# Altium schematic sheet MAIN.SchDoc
size A1; SheetNumber: 2; SheetTotal: 3
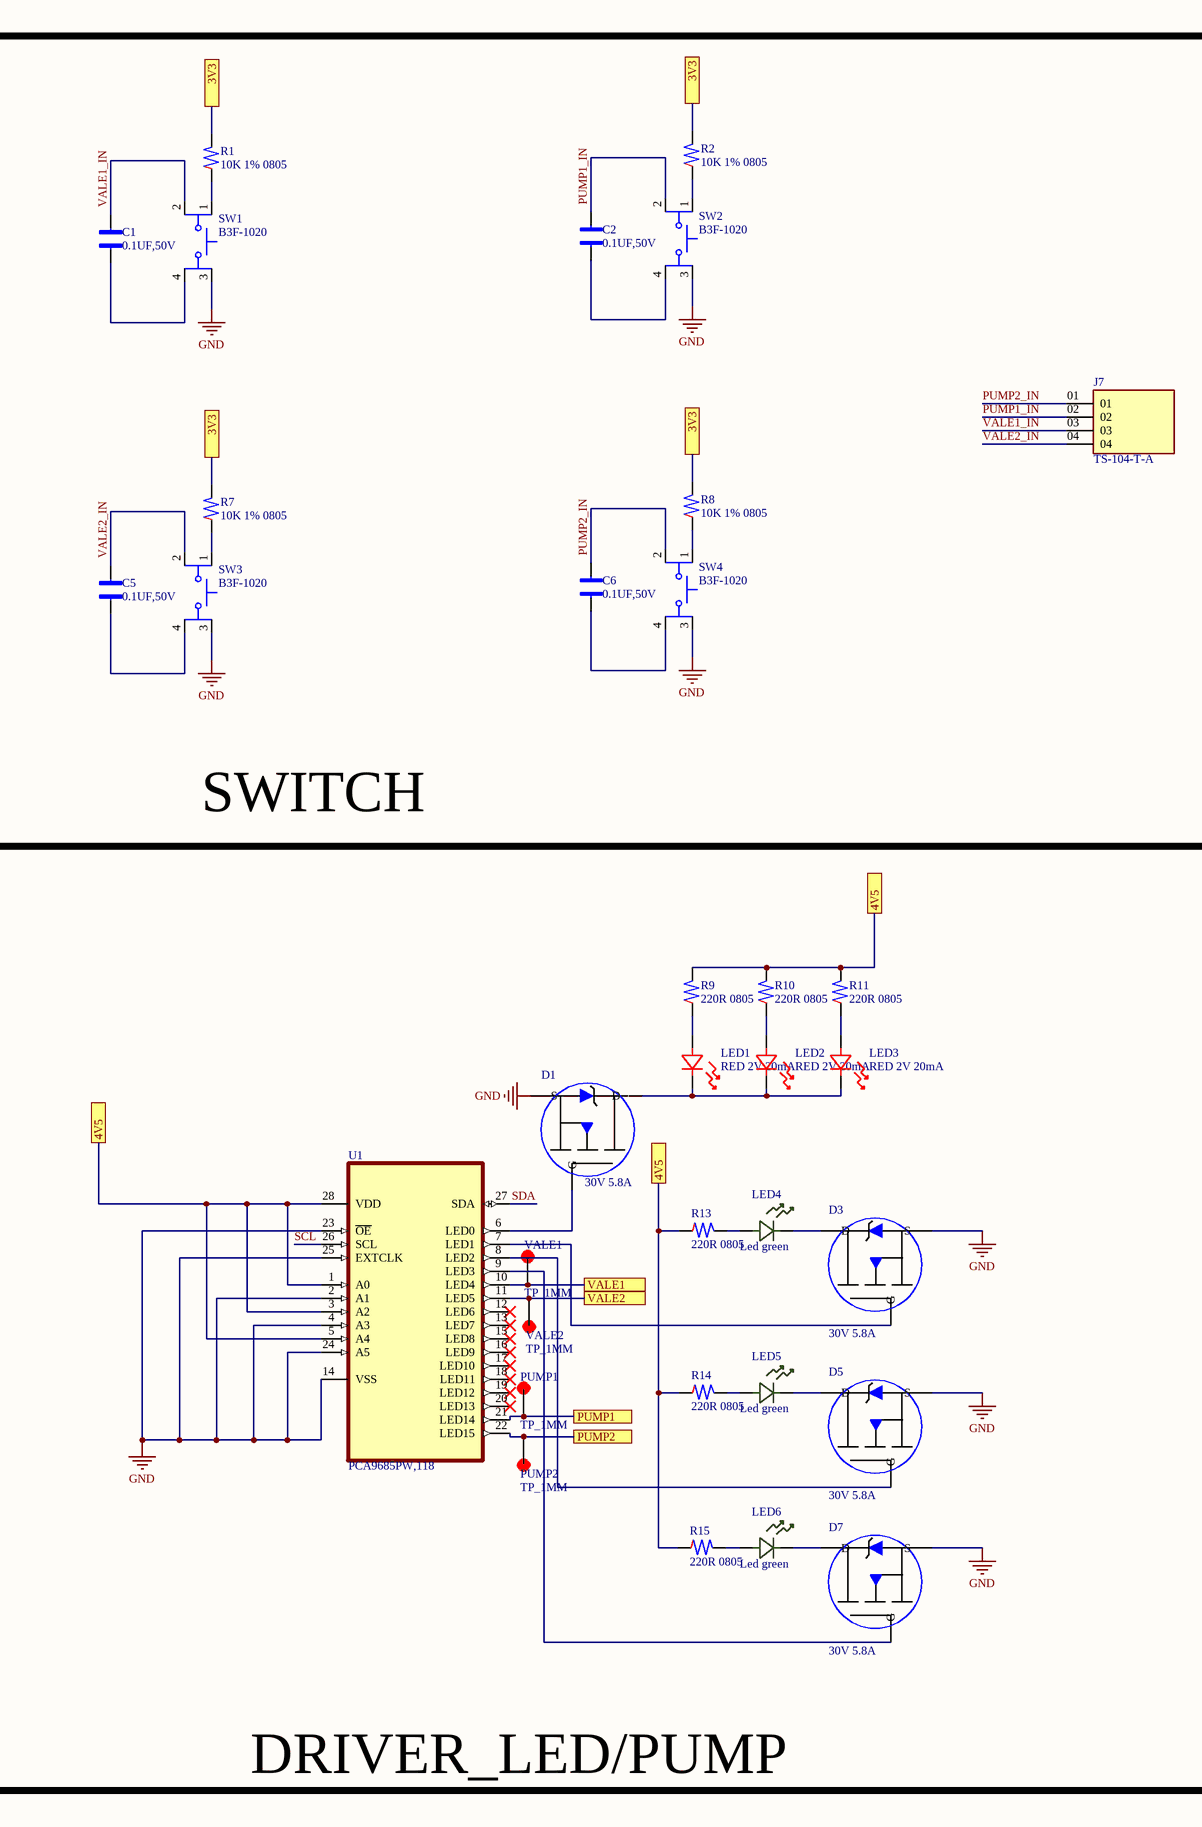
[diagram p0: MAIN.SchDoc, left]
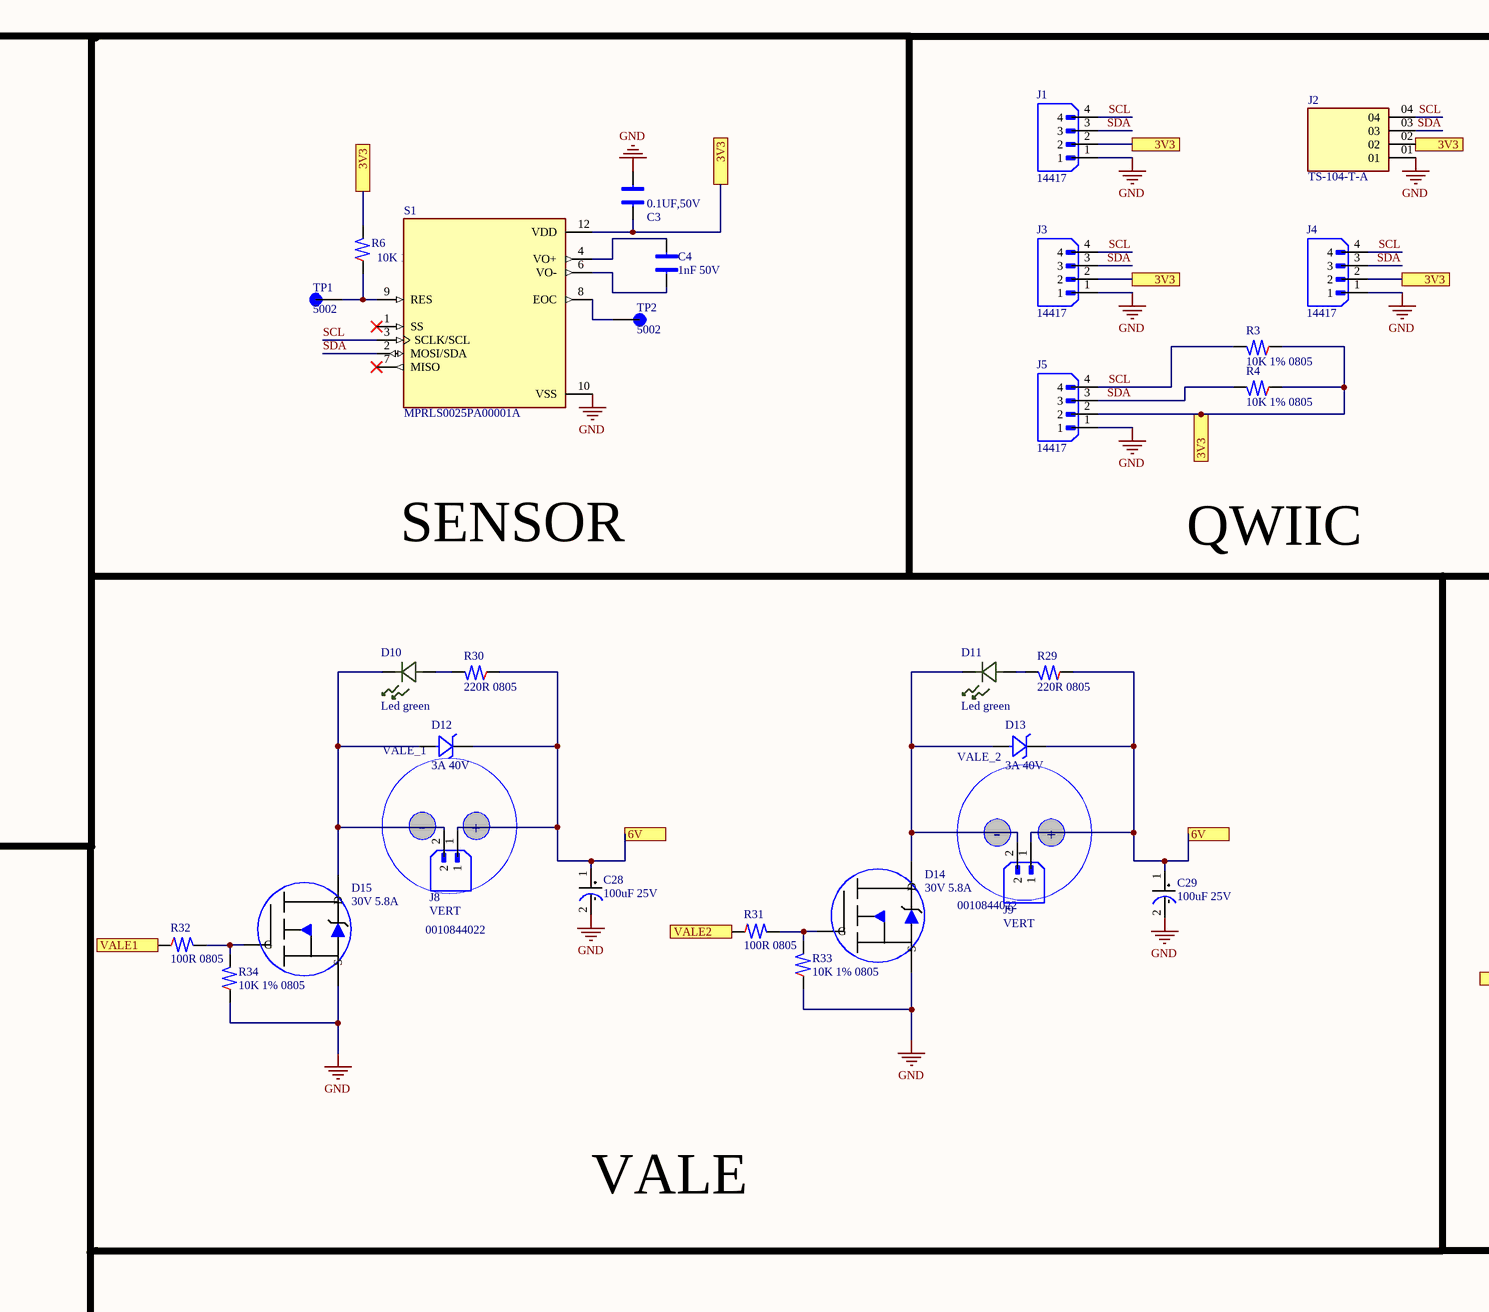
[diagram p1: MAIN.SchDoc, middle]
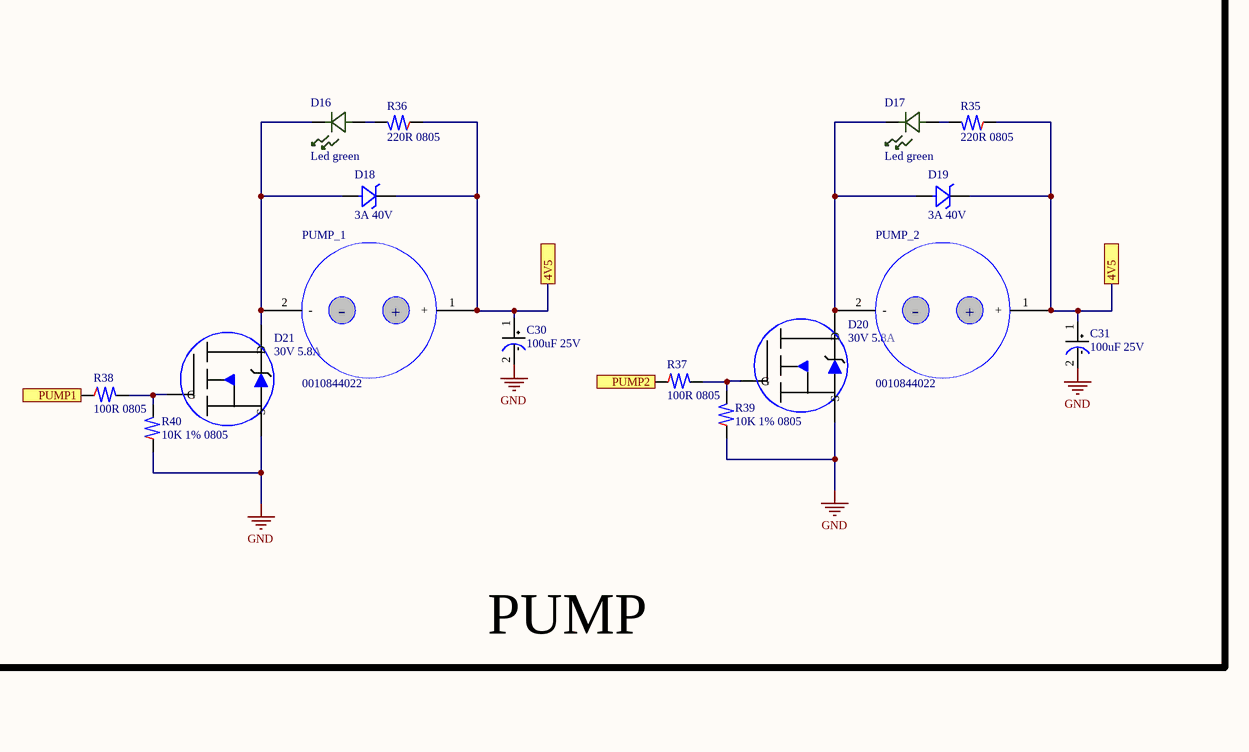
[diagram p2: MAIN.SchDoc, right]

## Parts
C1  0.1UF,50V  [CAP_CER_0805]
C2  0.1UF,50V  [CAP_CER_0805]
C3  0.1UF,50V  [CAP_CER_0805]
C4  1nF 50V  [CAP_CER_0805]
C5  0.1UF,50V  [CAP_CER_0805]
C6  0.1UF,50V  [CAP_CER_0805]
C28  100uF 25V  [CAP_ALUM_SMD_D10_H12.4]
C29  100uF 25V  [CAP_ALUM_SMD_D10_H12.4]
C30  100uF 25V  [CAP_ALUM_SMD_D10_H12.4]
C31  100uF 25V  [CAP_ALUM_SMD_D10_H12.4]
D1  30V 5.8A  [SOT-23-3]
D3  30V 5.8A  [SOT-23-3]
D5  30V 5.8A  [SOT-23-3]
D7  30V 5.8A  [SOT-23-3]
D10  Led green  [LED_LS R976_AOS]
D11  Led green  [LED_LS R976_AOS]
D12  3A 40V  [DO214AA]
D13  3A 40V  [DO214AA]
D14  30V 5.8A  [SOT-23-3]
D15  30V 5.8A  [SOT-23-3]
D16  Led green  [LED_LS R976_AOS]
D17  Led green  [LED_LS R976_AOS]
D18  3A 40V  [DO214AA]
D19  3A 40V  [DO214AA]
D20  30V 5.8A  [SOT-23-3]
D21  30V 5.8A  [SOT-23-3]
J1  14417  [SPARKFUN_PRT-14417]
J2  TS-104-T-A  [HDR_THT_1x04_P2.54]
J3  14417  [SPARKFUN_PRT-14417]
J4  14417  [SPARKFUN_PRT-14417]
J5  14417  [SPARKFUN_PRT-14417]
J7  TS-104-T-A  [HDR_THT_1x04_P2.54]
J8  VERT  [CONN_SMD_TOP_P2.50]
J9  VERT  [CONN_SMD_TOP_P2.50]
LED1  RED 2V 20mA  [LED_LS R976_AOS]
LED2  RED 2V 20mA  [LED_LS R976_AOS]
LED3  RED 2V 20mA  [LED_LS R976_AOS]
LED4  Led green  [LED_LS R976_AOS]
LED5  Led green  [LED_LS R976_AOS]
LED6  Led green  [LED_LS R976_AOS]
PUMP1  TP_1MM  [TP_1mm]
PUMP2  TP_1MM  [TP_1mm]
PUMP_1  0010844022  [PUMP_LPM - ZR370-02PM]
PUMP_2  0010844022  [PUMP_LPM - ZR370-02PM]
R1  10K 1% 0805  [RES_0805]
R2  10K 1% 0805  [RES_0805]
R3  10K 1% 0805  [RES_0805]
R4  10K 1% 0805  [RES_0805]
R6  10K 1% 0805  [RES_0805]
R7  10K 1% 0805  [RES_0805]
R8  10K 1% 0805  [RES_0805]
R9  220R 0805  [RES_0805]
R10  220R 0805  [RES_0805]
R11  220R 0805  [RES_0805]
R13  220R 0805  [RES_0805]
R14  220R 0805  [RES_0805]
R15  220R 0805  [RES_0805]
R29  220R 0805  [RES_0805]
R30  220R 0805  [RES_0805]
R31  100R 0805  [RES_0805]
R32  100R 0805  [RES_0805]
R33  10K 1% 0805  [RES_0805]
R34  10K 1% 0805  [RES_0805]
R35  220R 0805  [RES_0805]
R36  220R 0805  [RES_0805]
R37  100R 0805  [RES_0805]
R38  100R 0805  [RES_0805]
R39  10K 1% 0805  [RES_0805]
R40  10K 1% 0805  [RES_0805]
S1  MPRLS0025PA00001A  [XDCR_MPRLS0025PA00001A]
SW1  B3F-1020  [SW_B3F-1000_OMR]
SW2  B3F-1020  [SW_B3F-1000_OMR]
SW3  B3F-1020  [SW_B3F-1000_OMR]
SW4  B3F-1020  [SW_B3F-1000_OMR]
TP1  5002  [KEYSTONE_5002]
TP2  5002  [KEYSTONE_5002]
U1  PCA9685PW,118  [TSSOP-28]
VALE1  TP_1MM  [TP_1mm]
VALE2  TP_1MM  [TP_1mm]
VALE_1  0010844022  [VALE_FA0520E]
VALE_2  0010844022  [VALE_FA0520E]

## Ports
3V3, 4V5, 6V, PUMP1, PUMP2, VALE1, VALE2

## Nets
GND: C3.2 C28.2 C29.2 C30.2 C31.2 D1.2(S) D3.2(S) D5.2(S) D7.2(S) D14.2(S) D15.2(S) D20.2(S) D21.2(S) J1.1 J2.01 J3.1 J4.1 J5.1 R33.1 R34.1 R39.1 R40.1 S1.10(VSS) SW1.3 SW2.3 SW3.3 SW4.3 U1.2(A1) U1.4(A3) U1.14(VSS) U1.23(~{OE}) U1.24(A5) U1.25(EXTCLK)
3V3: C3.1 J1.2 J2.02 J3.2 J4.2 J5.2 R1.2 R2.2 R3.1 R4.1 R6.2 R7.2 R8.2 S1.12(VDD) ; port 3V3
4V5: C30.1 C31.1 D18.1(CATHODE) D19.1(CATHODE) PUMP_1.1(+) PUMP_2.1(+) R9.2 R10.2 R11.2 R13.1 R14.1 R15.1 R35.1 R36.1 U1.1(A0) U1.3(A2) U1.5(A4) U1.28(VDD) ; port 4V5
6V: C28.1 C29.1 D12.1(CATHODE) D13.1(CATHODE) J8.1 J9.1 R29.1 R30.1 ; port 6V
PUMP1: PUMP1.1 R38.1 U1.21(LED14) ; port PUMP1
PUMP1_IN: C2.2 J7.02 SW2.2
PUMP2: PUMP2.1 R37.1 U1.22(LED15) ; port PUMP2
PUMP2_IN: C6.2 J7.01 SW4.2
SCL: J1.4 J2.04 J3.4 J4.4 J5.4 R3.2 S1.3(SCLK/SCL) U1.26(SCL)
SDA: J1.3 J2.03 J3.3 J4.3 J5.3 R4.2 S1.2(MOSI/SDA) U1.27(SDA)
VALE1: R32.1 U1.10(LED4) VALE1.1 ; port VALE1
VALE1_IN: C1.2 J7.03 SW1.2
VALE2: R31.1 U1.11(LED5) VALE2.1 ; port VALE2
VALE2_IN: C5.2 J7.04 SW3.2
NetC1_1: C1.1 SW1.4
NetC2_1: C2.1 SW2.4
NetC4_1: C4.1 S1.6(VO-)
NetC4_2: C4.2 S1.4(VO+)
NetC5_1: C5.1 SW3.4
NetC6_1: C6.1 SW4.4
NetD1_1: D1.1(G) U1.6(LED0)
NetD1_3: D1.3(D) LED1.1 LED2.1 LED3.1
NetD3_1: D3.1(G) U1.7(LED1)
NetD3_3: D3.3(D) LED4.1
NetD5_1: D5.1(G) U1.8(LED2)
NetD5_3: D5.3(D) LED5.1
NetD7_1: D7.1(G) U1.9(LED3)
NetD7_3: D7.3(D) LED6.1
NetD10_1: D10.1 D12.2(ANODE) D15.3(D) J8.2
NetD10_2: D10.2 R30.2
NetD11_1: D11.1 D13.2(ANODE) D14.3(D) J9.2
NetD11_2: D11.2 R29.2
NetD14_1: D14.1(G) R31.2 R33.2
NetD15_1: D15.1(G) R32.2 R34.2
NetD16_1: D16.1 D18.2(ANODE) D21.3(D) PUMP_1.2(-)
NetD16_2: D16.2 R36.2
NetD17_1: D17.1 D19.2(ANODE) D20.3(D) PUMP_2.2(-)
NetD17_2: D17.2 R35.2
NetD20_1: D20.1(G) R37.2 R39.2
NetD21_1: D21.1(G) R38.2 R40.2
NetLED1_2: LED1.2 R9.1
NetLED2_2: LED2.2 R10.1
NetLED3_2: LED3.2 R11.1
NetLED4_2: LED4.2 R13.2
NetLED5_2: LED5.2 R14.2
NetLED6_2: LED6.2 R15.2
NetR1_1: R1.1 SW1.1
NetR2_1: R2.1 SW2.1
NetR6_1: R6.1 S1.9(RES) TP1.TP
NetR7_1: R7.1 SW3.1
NetR8_1: R8.1 SW4.1
NetS1_8: S1.8(EOC) TP2.TP

Not connected (* = marked no-connect by the designer): S1 1(SS)* 7(MISO)*; U1 12(LED6)* 13(LED7)* 15(LED8)* 16(LED9)* 17(LED10)* 18(LED11)* 19(LED12)* 20(LED13)*

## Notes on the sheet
- SENSOR
- QWIIC
- SWITCH
- VALE
- PUMP
- DRIVER_LED/PUMP

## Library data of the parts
C1-C3 C5 C6 = CAP_CER, 0805, X7R, 0.1UF, 5%, 50V: Ceramic Capacitor, Multilayer, Ceramic, 50V, 10% +Tol, 10% -Tol, X7R, 15% TC, 0.1uF, Surface Mount, 0805; Manufacturer: Nextgen; Manufacturer Part Number: 0805B104K500BD; Capacitance: 100nF; LIB MADE BY: MR HOANG
C4 = CAP_CER 0805 1NF 50V ULTRA STABL: Cap Ceramic 0.001uF 50V X8R 10% Pad SMD 0805 150C T/R Automotive AEC-Q200; Manufacturer: Yageo Group; Manufacturer Part Number: C0805C102K5HACAUTO; Temperature Coefficient: 30ppm/°C; LIB MADE BY: MR HOANG
C28-C31 = CAP ALUM POLY 100UF 20% 25V SMD: WCAP-PSLC Aluminum Polymer Capacitors; Manufacturer: Wurth Elektronik; Manufacturer Part Number: 875075561005; Manufacturer Lifecycle Status: ACTIVE; Capacitance: 100µF; ESR (Equivalent Series Resistance): 15mΩ; Leakage Current: 500µA; Life (Hours): 2000hours; Pitch: 10.3mm; Polarity: Polar; Ripple Current: 4.8A; Tolerance: 20%; YEOL: 1 = Estimated lifetime > 10 years; LIB MADE BY: MR HOANG
D1 D3 D5 D7 D14 D15 D20 D21 = MOSFET N-CH 30V 5.8A SOT23-3: Trans MOSFET N-CH 30V 5.7A 3-Pin SOT-23; Manufacturer: Alpha & Omega Semiconductor; Manufacturer Part Number: AO3400A; Drain to Source Resistance: 26.5mΩ; Gate to Source Voltage (Vgs): 12V; Input Capacitance: 630pF; Max Junction Temperature (Tj): 150°C; Max Power Dissipation: 1.4W; Number of Channels: 1; Threshold Voltage: 650mV; Turn-Off Delay Time: 25ns; Turn-On Delay Time: 3ns; LIB MADE BY: MR HOANG
D10 D11 D16 D17 LED4-LED6 = LED GREEN CLEAR CHIP SMD: Single-color LEDs; LITEON; LTST-C190GKT; Green; 130 °; 2.1 V; 0603; Manufacturer: Diodes Inc.; Current: 1A; Dominant Wavelength: 569nm; Forward Current: 30mA; Forward Voltage: 2.6V; Lens Color: Clear, Colorless; Lens Style: Clear; Luminous Intensity: 1.8mcd; Number of Circuits: 1; Peak Wavelength: 565nm; Power Dissipation: 100mW; Reverse Voltage: 5V; Shape: Rectangular; Test Current: 10mA; Viewing Angle: 130°; Voltage: 2V; LIB MADE BY: MR HOANG
D12 D13 D18 D19 = DIODE SCHOTTKY 40V 3A DO214AB: Rectifier Diode, Schottky, 1 Phase, 1 Element, 3A, 40V V(RRM), Silicon, DO-214AB; Manufacturer: onsemi; Manufacturer Part Number: SS34; Manufacturer Lifecycle Status: ACTIVE; Element Configuration: Single; Forward Voltage: 500mV; Max Forward Surge Current (Ifsm): 100A; Max Junction Temperature (Tj): 150°C; Max Power Dissipation: 2.27W; Max Reverse Leakage Current: 500µA; Number of Elements: 1; Peak Reverse Current: 20mA; Polarity: Standard; LIB MADE BY: MR HOANG
J1 J3-J5 = QWIIC CONNECTOR SMD 4-PIN: Manufacturer: SparkFun; LIB MADE BY: MR HOANG
J2 J7 = CONN HEADER VERT 4POS 2.54MM: Samtec 2.54mmpitch4pSingle row pin header, TSseries, right angle, Through hole mounting; Manufacturer Lifecycle Status: PRODUCTION; Gender: Male; Number of Contacts: 4; Pitch: 2.54mm; LIB MADE BY: MR HOANG
J8 J9 = CONN HEADER VERT 2POS 2.5MM: Board Connector, 2 Contact(s), 1 Row(s), Male, Straight, Solder Terminal; Manufacturer: JST; Manufacturer Part Number: B2B-XH-A; Contact Resistance: 20mΩ; Current Rating: 3A; Insulation Resistance: 1GΩ; LIB MADE BY: MR HOANG
LED1-LED3 = LED RED DIFFUSED 0805 SMD: Red 633nm LED Indication - Discrete 2V 0805 (2012 Metric); Manufacturer: Osram; Manufacturer Part Number: LS R976-NR-1-0-20-R18; LIB MADE BY: MR HOANG
PUMP_1 PUMP_2 = Air Pump and Vacuum DC Motor - 4.5 V and 2.5 LPM - ZR370-02PM: Connector Header 2 Position 6.35mm Solder Straight Thru-Hole 2 Terminal 1 Port MLX-Series; Manufacturer: Molex; Manufacturer Lifecycle Status: ACTIVE; Connector Type: Power; Contact Resistance: 3.5mΩ; Current Rating: 13.5A; Dielectric Material: Polyester; Gender: Female; Glow Wire Compliant: Non-compliant; Insulation Resistance: 1GΩ; Number of Circuits: 2; Operating Force: 6.672N; Plating: Tin; Plating Thickness: 3.5052µm; Ratings: CSA; Voltage Rating: 600V; LIB MADE BY: MR HOANG
R1-R4 R6-R8 R33 R34 R39 R40 = RES_SMD 10K 1% 1/4W 0805: Res Thick Film 0805 10K Ohm 1% 0.125W(1/8W) ±100ppm/C Pad SMD Automotive T/R; Manufacturer: Vishay; Manufacturer Part Number: CRCW080510K0FKEA; Manufacturer Package Identifier: CRCW0805-e3; Power Dissipation: 125mW; Power Rating: 120mW; Resistance: 10kΩ; Temperature Coefficient: 100ppm/°C; Voltage Rating: 150V; LIB MADE BY: MR HOANG
R9-R11 R13-R15 R29 R30 R35 R36 = RES_SMD 220 OHM 1% 1/8W 0805: Res Thick Film 0805 220 Ohm 1% 0.125W(1/8W) ±100ppm/C Pad SMD Automotive T/R; Manufacturer: TE Connectivity; Manufacturer Part Number: CRGCQ0805F220R; Manufacturer Lifecycle Status: ACTIVE; Operating Supply Voltage: 150V; Power Rating: 125mW; Resistance: 220Ω; Temperature Coefficient: 100ppm/°C; LIB MADE BY: MR HOANG
R31 R32 R37 R38 = RES_SMD 100 OHM 1% 1/8W 0805: Resistor Thick Film 0805 100 Ohm 1% 1/8W 100ppm/C Molded SMD Punched Carrier T/R; Manufacturer: Panasonic; Manufacturer Part Number: ERJ6ENF1000V; Manufacturer Lifecycle Status: ACTIVE; Manufacturer Package Identifier: 0805 (2012 metric); Part Series: Precision Thick Film Chip Resistors; Max Power Dissipation: 125mW; Resistance: 100Ω; Temperature Coefficient: 100ppm/°C; Voltage Rating: 150V; LIB MADE BY: MR HOANG
S1 = SENSOR 25PSIA 0.1" 24BIT: Board Mount Pressure Sensor -0.3V to 3.9V 0psi to 25psi Absolute 12-Pin T/R; Manufacturer: Honeywell; Accuracy: 0.25%; Current Rating: 1.7mA; Max Supply Voltage: 3.6V; Min Supply Voltage: 1.8V; Number of Bits: 14; Operating Supply Current: 33.8µA; Port Style: Barbless; LIB MADE BY: MR HOANG
SW1-SW4 = SWITCH TACTILE SPST-NO 0.05A 24V: Switch Tactile N.O. SPST Flat Round Button PC Pins 0.05A 24VDC 0.98N Thru-Hole Bag; Manufacturer: Omron; Actuator Length: 900µm; Contact Current Rating: 50mA; Contact Resistance: 100mΩ; Electrical Life: 1Mcycles; Illumination Type: Illuminated, Non-Illuminated; Max Voltage Rating (DC): 24V; Number of Poles: 1; Operating Force: 1.27N; Switch Function: Off-Mom; Switch Travel: 250µm; LIB MADE BY: MR HOANG
TP1 TP2 = PC TEST POINT MINIATURE WHITE: Test Point, Mini, Thm, Pc, .300 L, .100 Od, Heat Resistant Nylon 46, White; Manufacturer: Keystone; Body Material: Bronze, PBT; Hole Diameter: 1.6mm; Inside Diameter: 1.27mm; Insulation: Insulated; Number of Ports: 1; Outside Diameter: 2.54mm; Plating: Silver; LIB MADE BY: MR HOANG
U1 = IC LED DRVR LIN PWM 25MA 28TSSOP: PCA9685 Series 5.5V 25 mA 1 MHz 12-bit PWM Fm+I2C-Bus LED Controller - TSSOP-28; Manufacturer: NXP Semiconductors; Frequency: 25MHz; High Level Output Current: 10mA; Low Level Output Current: 400A; Max Power Dissipation: 400mW; Min Supply Voltage: 2.3V; Nominal Supply Current: 6mA; Nominal Supply Voltage (DC): 3V; Number of Characters: 16; Number of Circuits: 1; Output Current: 25mA; Output Voltage: 5V; Power Dissipation: 400W; LIB MADE BY: MR HOANG
VALE_1 VALE_2 = 6V Air Valve with 2-pin JST XH Connector - FA0520E: Connector Header 2 Position 6.35mm Solder Straight Thru-Hole 2 Terminal 1 Port MLX-Series; Manufacturer: Molex; Manufacturer Lifecycle Status: ACTIVE; Connector Type: Power; Contact Resistance: 3.5mΩ; Current Rating: 13.5A; Dielectric Material: Polyester; Gender: Female; Glow Wire Compliant: Non-compliant; Insulation Resistance: 1GΩ; Number of Circuits: 2; Operating Force: 6.672N; Plating: Tin; Plating Thickness: 3.5052µm; Ratings: CSA; Voltage Rating: 600V; LIB MADE BY: MR HOANG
